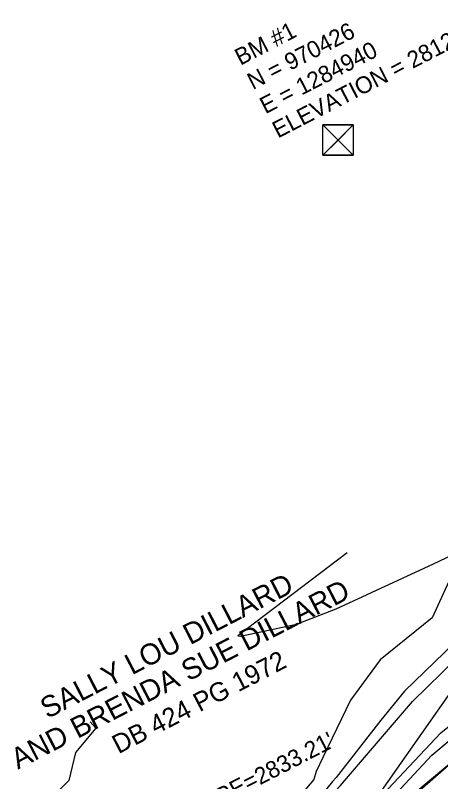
# Model space of a CAD drawing. Extents: x 1284446 to 1285480, y 969739 to 970628.
# Drawn here: x 1284863.5 to 1284964.9, y 970273.5 to 970455.9 of the extents above; entities that cross this region are included whole.
import ezdxf

# ---------------------------------------------------------------- set-up
doc = ezdxf.new("R2010")
doc.units = 0
for name, color, linetype in [('CTL Vertical Benchmark CELL', 7, 'Continuous'), ('CTL Vertical Benchmark Text', 7, 'Continuous'), ('Default', 7, 'Continuous'), ('Exist Hydro Jurisdictional Stream or Body of Water', 7, 'Continuous'), ('Exist Other Culture Fence Line', 7, 'Continuous'), ('Exist Property Deed Book Text', 7, 'Continuous'), ('Exist Property Owner Text', 7, 'Continuous'), ('Exist Utilities Other Located Object Text', 7, 'Continuous'), ('Exist Vegetation Woods Line', 7, 'Continuous')]:
    doc.layers.add(name, color=color, linetype=linetype)

msp = doc.modelspace()

# ---------------------------------------------------------------- linework, layer by layer
at = {"layer": 'CTL Vertical Benchmark CELL'}
msp.add_line((1284940.42, 970426.24), (1284940.42, 970426.24), dxfattribs=at)
msp.add_lwpolyline([(1284936.82, 970429.83), (1284944.01, 970429.83), (1284944.01, 970422.64), (1284936.82, 970422.64)], close=True, dxfattribs=at)
for points in [[(1284944.01, 970429.83), (1284936.82, 970422.64), (1284940.42, 970426.24), (1284944.01, 970422.64), (1284936.82, 970429.83)], [(1284940.42, 970426.24), (1284944.01, 970429.83), (1284936.82, 970429.83), (1284940.42, 970426.24)], [(1284940.42, 970426.24), (1284936.82, 970422.64), (1284944.01, 970422.64), (1284940.42, 970426.24)]]:
    msp.add_lwpolyline(points, dxfattribs=at)
at = {"layer": 'Default'}
for points in [[(1284993.35, 970338.77), (1284991.97, 970336.22), (1284985.77, 970331.04), (1284969.06, 970325.96), (1284962.85, 970312.44), (1284950.45, 970302.48), (1284943.38, 970292.88), (1284936.84, 970279.39), (1284935.16, 970275.9), (1284934.66, 970273.98), (1284929.48, 970267.89)], [(1284942.61, 970327.96), (1284916.56, 970308.22), (1284917.2, 970308.11), (1284930.49, 970310.97), (1284939.93, 970314.64), (1284963.11, 970325.3), (1284967.65, 970327.5), (1284969.65, 970328.73), (1284978, 970334.3)], [(1284957.73, 970270.03), (1284971.01, 970281.14), (1284973.1, 970282.91), (1284979.04, 970288.11), (1284991.31, 970298.93), (1284992.31, 970299.76), (1285008.11, 970310.05), (1285009.58, 970311.09), (1285032.27, 970326.55), (1285033.3, 970327.28), (1285034.75, 970328.26), (1285037.25, 970330.36)], [(1284970.56, 970308.81), (1284956.23, 970295.03), (1284950.64, 970288.15), (1284939.95, 970274.47), (1284939.11, 970273.49), (1284931.71, 970264.36)], [(1284881.33, 970287.73), (1284882.73, 970286.19), (1284877.83, 970280.38), (1284876.27, 970273.74), (1284869.62, 970267.09)], [(1284948.95, 970264.94), (1284962.76, 970279.8), (1284967.14, 970283.46)]]:
    msp.add_lwpolyline(points, dxfattribs=at)
at = {"layer": 'Exist Hydro Jurisdictional Stream or Body of Water'}
for points in [[(1284873.19, 970156.9), (1284883.51, 970166.48), (1284889.94, 970172.96), (1284895.44, 970190.43), (1284903.3, 970205.95), (1284913.73, 970232), (1284923.66, 970254.25), (1284941.01, 970272.57), (1284958.16, 970292.53), (1284979.26, 970313.17), (1284998.61, 970327.4), (1285021.77, 970343.41), (1285038.64, 970357.96), (1285060.69, 970382.43), (1285077.07, 970403.68), (1285083.99, 970417.36), (1285093.67, 970433.2), (1285120.38, 970455.77)], [(1284898.55, 970093.67), (1284891.93, 970104.57), (1284887.09, 970113.68), (1284882.06, 970129.58), (1284887.8, 970135.61), (1284894.46, 970156.08), (1284893.69, 970164.51), (1284897.37, 970171.05), (1284903.86, 970179.35), (1284904.34, 970180.6), (1284915.98, 970216.96), (1284921.11, 970228.41), (1284932.56, 970248.17), (1284947.31, 970266.45), (1284964.91, 970285.06), (1284987.35, 970303.2), (1285005.06, 970315.3), (1285028.92, 970334.49), (1285047.82, 970349.99), (1285069.69, 970374.61), (1285084.31, 970397.98), (1285093.11, 970411.54), (1285103.27, 970427.02), (1285126.73, 970448.14)]]:
    msp.add_lwpolyline(points, dxfattribs=at)
at = {"layer": 'Exist Other Culture Fence Line'}
msp.add_lwpolyline([(1285182.44, 970426.98), (1285127.53, 970386.93), (1285081.55, 970356.81), (1285037.11, 970332.56), (1285005.28, 970312.73), (1284979.02, 970288.01), (1284954.93, 970267.09)], dxfattribs=at)
at = {"layer": 'Exist Vegetation Woods Line'}
msp.add_lwpolyline([(1285171.52, 970440.57), (1285121.64, 970393.92), (1285081.63, 970356.87), (1285045.47, 970320.17), (1285013.5, 970297.41), (1284993.36, 970280.22), (1284932.55, 970245.36), (1284996.18, 970336), (1285054.45, 970386.33), (1285100.52, 970417.69), (1285131.32, 970449.81)], dxfattribs=at)

# ---------------------------------------------------------------- texts
at = {"layer": 'CTL Vertical Benchmark Text'}
for s, p in [("ELEVATION = 2812.79'", (1284926.08, 970426.58)), ('BM #1', (1284917.13, 970443.91)), ('N = 970426', (1284920.11, 970438.13)), ('E = 1284940', (1284923.1, 970432.36))]:
    msp.add_text(s, height=4, rotation=27.3235, dxfattribs=at).set_placement(p)
at = {"layer": 'Exist Property Deed Book Text'}
msp.add_text('DB 424 PG 1972', height=4.5, rotation=27.3235, dxfattribs=at).set_placement((1284888.09, 970279.99))
at = {"layer": 'Exist Property Owner Text'}
for s, p in [('SALLY LOU DILLARD', (1284871.15, 970288.36)), ('AND BRENDA SUE DILLARD', (1284864.14, 970276.3))]:
    msp.add_text(s, height=5, rotation=27.3235, dxfattribs=at).set_placement(p)
at = {"layer": 'Exist Utilities Other Located Object Text'}
msp.add_text("LOW WIRE=2833.21'", height=4, rotation=27.3235, dxfattribs=at).set_placement((1284894.47, 970258.48))

doc.saveas('drawing.dxf')
